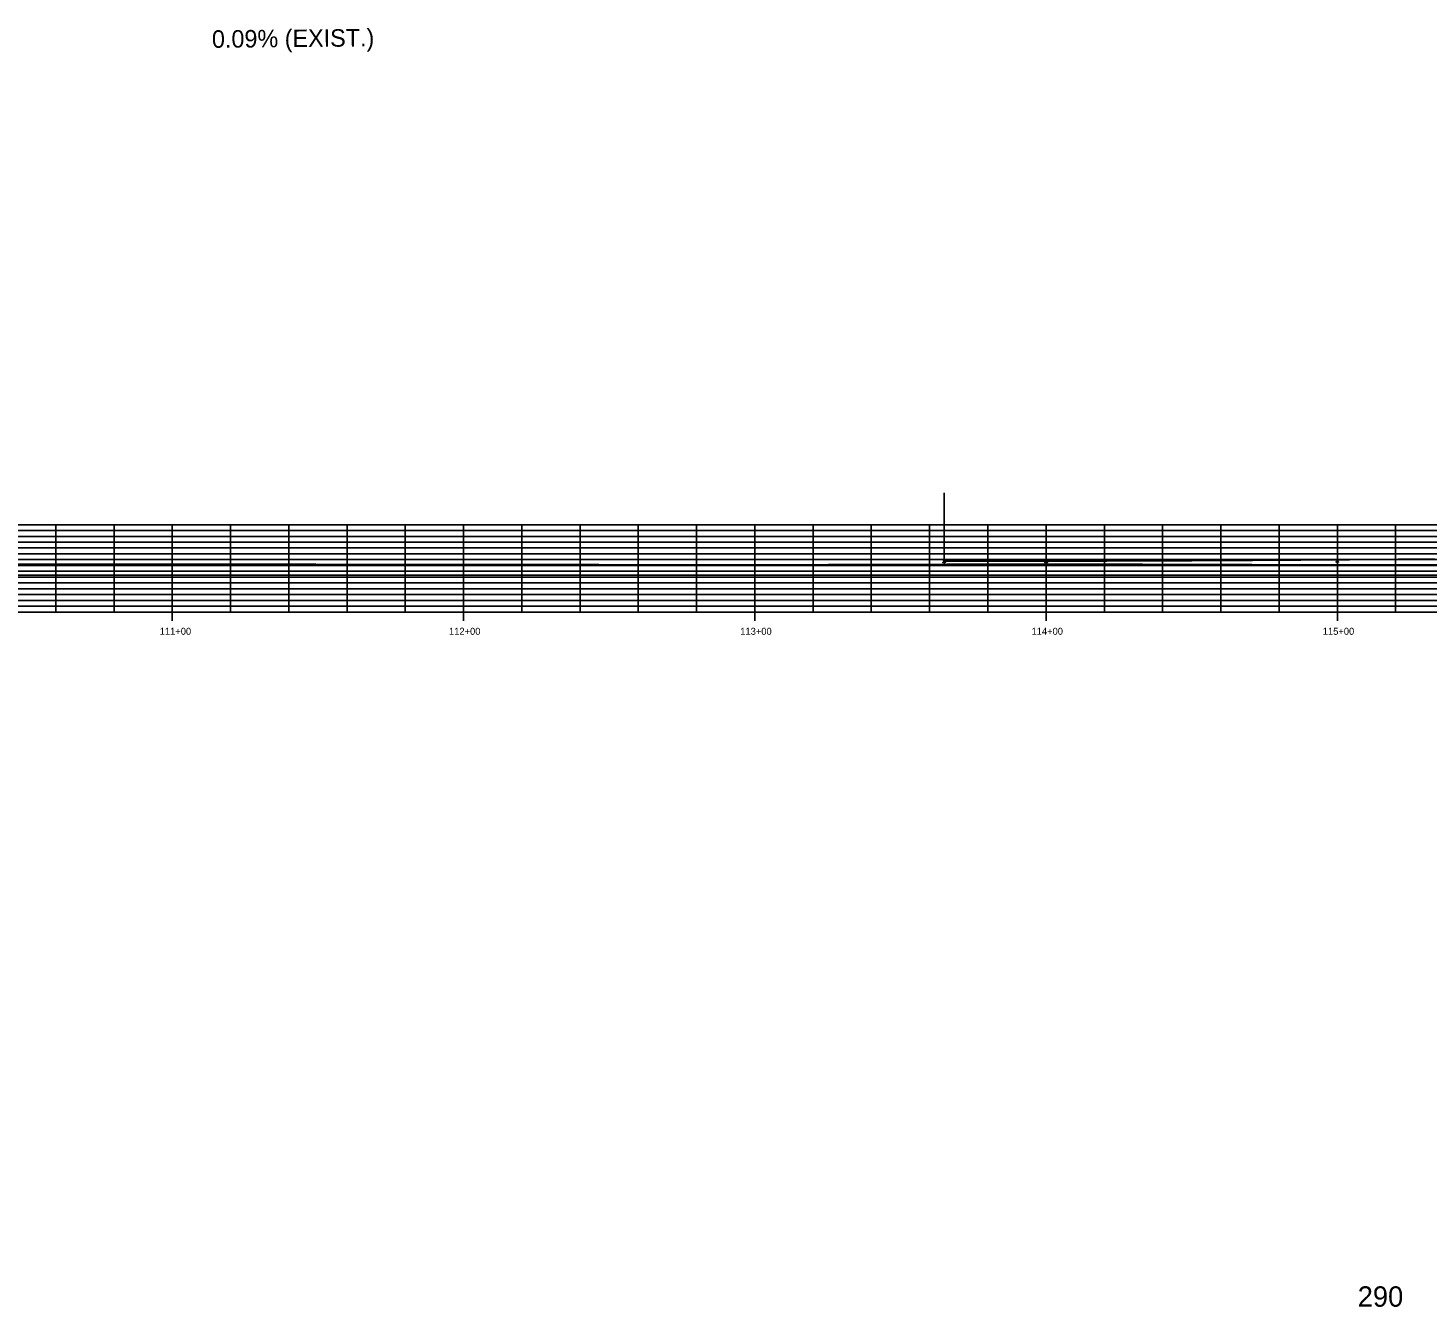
# Model space of a CAD drawing. Extents: x 1676565 to 1681112, y 227357 to 229815.
# Drawn here: x 1679217.8 to 1679698.4, y 229350.2 to 229789.4 of the extents above; entities that cross this region are included whole.
import ezdxf

# ---------------------------------------------------------------- set-up
doc = ezdxf.new("R2010")
doc.units = 0
for name, color, linetype in [('Default', 7, 'Continuous'), ('R_Axis', 7, 'Continuous'), ('R_Axis Annot', 7, 'Continuous'), ('R_Exist Surface', 7, 'Continuous'), ('R_Grid', 7, 'Continuous'), ('R_Horz Alg Annot', 7, 'Continuous'), ('R_No Plot', 7, 'Continuous'), ('R_Point Sym', 7, 'Continuous'), ('R_Water', 7, 'Continuous')]:
    doc.layers.add(name, color=color, linetype=linetype)

msp = doc.modelspace()

# ---------------------------------------------------------------- linework, layer by layer
at = {"layer": 'Default'}
msp.add_line((1679532.31, 229606.27), (1679567.31, 229606.32), dxfattribs=at)
msp.add_lwpolyline([(1679567.31, 229606.32), (1679571.47, 229606.33), (1679575.64, 229606.33), (1679579.81, 229606.34), (1679583.97, 229606.35), (1679588.14, 229606.36), (1679592.31, 229606.38), (1679596.47, 229606.39), (1679600.64, 229606.4), (1679604.81, 229606.42), (1679608.97, 229606.44), (1679613.14, 229606.45), (1679617.31, 229606.47), (1679621.47, 229606.49), (1679625.64, 229606.51), (1679629.81, 229606.53), (1679633.97, 229606.56), (1679638.14, 229606.58), (1679642.31, 229606.61), (1679646.47, 229606.63), (1679650.64, 229606.66), (1679654.81, 229606.69), (1679658.97, 229606.72), (1679663.14, 229606.75), (1679671.47, 229606.81), (1679675.64, 229606.85), (1679679.81, 229606.88), (1679683.97, 229606.92), (1679688.14, 229606.96), (1679692.31, 229606.99), (1679696.47, 229607.03), (1679700.64, 229607.07)], dxfattribs=at)
at = {"layer": 'R_Axis'}
msp.add_line((1678167.31, 229588.83), (1681067.31, 229588.83), dxfattribs=at)
at = {"layer": 'R_Exist Surface'}
msp.add_lwpolyline([(1679212.02, 229605.22), (1679218.36, 229605.22), (1679219.49, 229605.22), (1679219.57, 229605.22), (1679226.96, 229605.23), (1679234.43, 229605.24), (1679240.83, 229605.25), (1679241.9, 229605.24), (1679241.91, 229605.24), (1679249.37, 229605.25), (1679253, 229605.26), (1679256.84, 229605.26), (1679264.31, 229605.27), (1679270.35, 229605.27), (1679271.01, 229605.27), (1679271.78, 229605.27), (1679279.25, 229605.27), (1679282.58, 229605.27), (1679282.91, 229605.27), (1679286.72, 229605.26), (1679294.19, 229605.26), (1679301.66, 229605.25), (1679305.97, 229605.24), (1679306.54, 229605.24), (1679307.09, 229605.24), (1679309.13, 229605.24), (1679316.6, 229605.22), (1679324.07, 229605.21), (1679324.46, 229605.21), (1679324.76, 229605.21), (1679331.54, 229605.2), (1679336.3, 229605.19), (1679336.77, 229605.19), (1679337.26, 229605.19), (1679339.01, 229605.19), (1679346.48, 229605.18), (1679353.95, 229605.17), (1679360.29, 229605.16), (1679360.54, 229605.16), (1679361.18, 229605.16), (1679361.42, 229605.16), (1679368.89, 229605.16), (1679376.36, 229605.15), (1679379.75, 229605.14), (1679380.17, 229605.15), (1679383.83, 229605.14), (1679389.46, 229605.14), (1679390.34, 229605.15), (1679391.3, 229605.14), (1679398.77, 229605.14), (1679404.23, 229605.13), (1679404.87, 229605.13), (1679406.24, 229605.12), (1679413.71, 229605.11), (1679421.18, 229605.09), (1679424.81, 229605.09), (1679425.5, 229605.08), (1679428.65, 229605.08), (1679436.12, 229605.06), (1679438.72, 229605.06), (1679439.47, 229605.05), (1679443.59, 229605.06), (1679451.06, 229605.05), (1679452.63, 229605.05), (1679453.88, 229605.05), (1679458.53, 229605.05), (1679466, 229605.04), (1679466.98, 229605.04), (1679467.73, 229605.04), (1679473.47, 229605.06), (1679479.52, 229605.07), (1679480.22, 229605.08), (1679480.94, 229605.08), (1679488.41, 229605.1), (1679492.05, 229605.1), (1679492.59, 229605.11), (1679495.88, 229605.12), (1679503.35, 229605.14), (1679504.58, 229605.15), (1679510.83, 229605.17), (1679518.3, 229605.19), (1679522.46, 229605.2), (1679522.66, 229605.2), (1679525.77, 229605.2), (1679531.65, 229605.21), (1679531.72, 229605.21), (1679533.24, 229605.22), (1679537.32, 229605.22), (1679540.71, 229605.23), (1679545.18, 229605.23), (1679545.24, 229605.23), (1679548.18, 229605.23), (1679555.65, 229605.24), (1679563.12, 229605.24), (1679565.22, 229605.24), (1679565.55, 229605.24), (1679570.59, 229605.24), (1679578.06, 229605.24), (1679579.6, 229605.24), (1679580.04, 229605.24), (1679585.53, 229605.24), (1679589.38, 229605.23), (1679589.64, 229605.23), (1679593, 229605.23), (1679600.47, 229605.22), (1679607.94, 229605.2), (1679608.16, 229605.2), (1679608.67, 229605.2), (1679615.41, 229605.18), (1679622.88, 229605.16), (1679627.45, 229605.14), (1679628.62, 229605.14), (1679630.35, 229605.13), (1679637.82, 229605.11), (1679637.94, 229605.11), (1679638.85, 229605.1), (1679645.29, 229605.08), (1679652.72, 229605.06), (1679652.76, 229605.06), (1679653.43, 229605.06), (1679660.23, 229605.04), (1679667.19, 229605.03), (1679667.7, 229605.03), (1679668.66, 229605.03), (1679675.17, 229605.02), (1679675.53, 229605.02), (1679682.64, 229605.03), (1679686.38, 229605.03), (1679687.33, 229605.03), (1679687.81, 229605.03), (1679690.11, 229605.03), (1679697.58, 229605.04), (1679705.05, 229605.05)], dxfattribs=at)
at = {"layer": 'R_Grid'}
for p, q in [((1678167.31, 229618.83), (1681067.31, 229618.83)), ((1678167.31, 229618.83), (1681067.31, 229618.83)), ((1678167.31, 229616.83), (1681067.31, 229616.83)), ((1679227.31, 229588.83), (1679227.31, 229618.83)), ((1679247.31, 229588.83), (1679247.31, 229618.83)), ((1679267.31, 229588.83), (1679267.31, 229618.83)), ((1679287.31, 229588.83), (1679287.31, 229618.83)), ((1679307.31, 229588.83), (1679307.31, 229618.83)), ((1679327.31, 229588.83), (1679327.31, 229618.83)), ((1679347.31, 229588.83), (1679347.31, 229618.83)), ((1679367.31, 229588.83), (1679367.31, 229618.83)), ((1679387.31, 229588.83), (1679387.31, 229618.83)), ((1679407.31, 229588.83), (1679407.31, 229618.83)), ((1679427.31, 229588.83), (1679427.31, 229618.83)), ((1679447.31, 229588.83), (1679447.31, 229618.83)), ((1679467.31, 229588.83), (1679467.31, 229618.83)), ((1679487.31, 229588.83), (1679487.31, 229618.83)), ((1679507.31, 229588.83), (1679507.31, 229618.83)), ((1679527.31, 229588.83), (1679527.31, 229618.83)), ((1679547.31, 229588.83), (1679547.31, 229618.83)), ((1679567.31, 229588.83), (1679567.31, 229618.83)), ((1679587.31, 229588.83), (1679587.31, 229618.83)), ((1679607.31, 229588.83), (1679607.31, 229618.83)), ((1679627.31, 229588.83), (1679627.31, 229618.83)), ((1679647.31, 229588.83), (1679647.31, 229618.83)), ((1679667.31, 229588.83), (1679667.31, 229618.83)), ((1679687.31, 229588.83), (1679687.31, 229618.83)), ((1678167.31, 229614.83), (1681067.31, 229614.83)), ((1678167.31, 229612.83), (1681067.31, 229612.83)), ((1678167.31, 229610.83), (1681067.31, 229610.83)), ((1678167.31, 229608.83), (1681067.31, 229608.83)), ((1678167.31, 229606.83), (1681067.31, 229606.83)), ((1678167.31, 229604.83), (1681067.31, 229604.83)), ((1678167.31, 229602.83), (1681067.31, 229602.83)), ((1678167.31, 229600.83), (1681067.31, 229600.83)), ((1678167.31, 229598.83), (1681067.31, 229598.83)), ((1678167.31, 229596.83), (1681067.31, 229596.83)), ((1678167.31, 229594.83), (1681067.31, 229594.83)), ((1678167.31, 229592.83), (1681067.31, 229592.83)), ((1678167.31, 229590.83), (1681067.31, 229590.83)), ((1679267.31, 229585.83), (1679267.31, 229588.83)), ((1679367.31, 229585.83), (1679367.31, 229588.83)), ((1679467.31, 229585.83), (1679467.31, 229588.83)), ((1679567.31, 229585.83), (1679567.31, 229588.83)), ((1679667.31, 229585.83), (1679667.31, 229588.83))]:
    msp.add_line(p, q, dxfattribs=at)
at = {"layer": 'R_No Plot'}
msp.add_line((1679532.31, 229605.38), (1679532.31, 229629.75), dxfattribs=at)
at = {"layer": 'R_Point Sym'}
for points in [[(1679532.31, 229606.27), (1679531.81, 229606.77), (1679532.31, 229606.27), (1679531.81, 229605.77), (1679532.31, 229606.27), (1679532.81, 229605.77), (1679532.31, 229606.27), (1679532.81, 229606.77)], [(1679567.31, 229606.32), (1679566.81, 229606.82), (1679567.31, 229606.32), (1679566.81, 229605.82), (1679567.31, 229606.32), (1679567.81, 229605.82), (1679567.31, 229606.32), (1679567.81, 229606.82)], [(1679667.31, 229606.47), (1679666.81, 229606.97), (1679667.31, 229606.47), (1679666.81, 229605.97), (1679667.31, 229606.47), (1679667.81, 229605.97), (1679667.31, 229606.47), (1679667.81, 229606.97)]]:
    msp.add_lwpolyline(points, dxfattribs=at)
at = {"layer": 'R_Water'}
msp.add_line((1681080.69, 229601.46), (1678154.35, 229601.46), dxfattribs=at)

# ---------------------------------------------------------------- texts
at = {"layer": 'R_Axis Annot'}
for s, height, p in [('111+00', 2.4, (1679262.99, 229581.03)), ('112+00', 2.4, (1679362.31, 229581.03)), ('113+00', 2.4, (1679462.31, 229581.03)), ('114+00', 2.4, (1679562.31, 229581.03)), ('115+00', 2.4, (1679662.31, 229581.03)), ('290', 7, (1679674.31, 229350.33)), ('290', 7, (1679674.31, 229350.33))]:
    msp.add_text(s, height=height, dxfattribs=at).set_placement(p)
at = {"layer": 'R_Horz Alg Annot'}
msp.add_text('0.09% (EXIST.)', height=6, rotation=0.5156, dxfattribs=at).set_placement((1679280.95, 229782.56))

doc.saveas('drawing.dxf')
